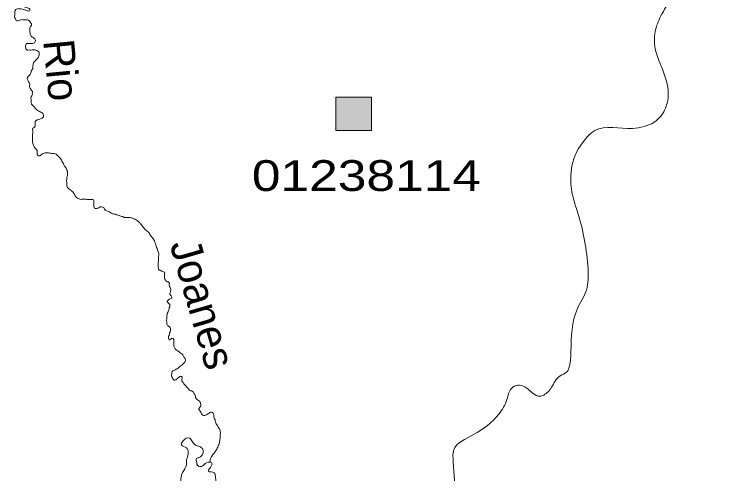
# Model space of a CAD drawing. Extents: x 854879 to 917879, y 8541948 to 8631048.
# Drawn here: x 893942 to 903256, y 8588549 to 8594513 of the extents above; entities that cross this region are included whole.
import ezdxf
from ezdxf.enums import TextEntityAlignment as Align

# ---------------------------------------------------------------- set-up
doc = ezdxf.new("R2010")
doc.units = 0
doc.header["$LTSCALE"] = 160
for name, color, linetype, lineweight in [('1', 7, 'Continuous', 13), ('12', 7, 'Continuous', 13), ('3', 7, 'Continuous', 13), ('63', 7, 'Continuous', 13)]:
    doc.layers.add(name, color=color, linetype=linetype, lineweight=lineweight)

msp = doc.modelspace()

# ---------------------------------------------------------------- hatches: boundary and pattern name
at = {"layer": '1'}
msp.add_hatch(color=256, dxfattribs=at).paths.add_polyline_path([(898118.1, 8593436.5), (898581.9, 8593436.5), (898581.9, 8593005.6), (898118.1, 8593005.6)])

# ---------------------------------------------------------------- linework, layer by layer
msp.add_lwpolyline([(898118.1, 8593436.5), (898581.9, 8593436.5), (898581.9, 8593005.6), (898118.1, 8593005.6)], close=True, dxfattribs=at)
at = {"layer": '12'}
msp.add_spline([(900643.9, 8584741.1), (900619.9, 8584871.4), (900626.7, 8585014), (900634.4, 8585228), (900780.5, 8585509.1), (900951, 8585695.6), (901064.4, 8585806.4), (901276.2, 8586035.7), (901382.7, 8586205.2), (901351.9, 8586399.2), (901212.2, 8586439.1), (901055.9, 8586586.3), (901008.8, 8586698.9), (900724.5, 8587015.8), (900510.3, 8587232.4), (900407, 8587327.9), (900324, 8587423.2), (900225.9, 8587541.6), (900060.1, 8587742.3), (899971.3, 8587779.1), (899833.8, 8587793.5), (899760.2, 8587824.9), (899717.6, 8587884.1), (899690.3, 8587948.1), (899670.9, 8588027.3), (899663.3, 8588246.6), (899640.6, 8588700.4), (899650.2, 8588860.9), (899902.3, 8589056.6), (900231.8, 8589322.8), (900338.6, 8589512.6), (900396.4, 8589657.2), (900478.5, 8589699.5), (900658.4, 8589608.2), (900741.9, 8589556.2), (900816, 8589570.6), (900916.6, 8589671.3), (901028, 8589817.8), (901115.3, 8589870.3), (901149.3, 8589946.3), (901169.4, 8590137.2), (901252.5, 8590691.7), (901370.1, 8590932.4), (901391.2, 8591209.9), (901259.6, 8591930.1), (901186.1, 8592183.3), (901168.7, 8592433.2), (901196.2, 8592601.1), (901235.7, 8592710.2), (901308.5, 8592829.1), (901478.8, 8593002.9), (901968.6, 8593032.7), (902119.3, 8593056.4), (902298.9, 8593151), (902374, 8593247), (902432.5, 8593450.1), (902372.4, 8593761.8), (902263.9, 8594071.4), (902261.4, 8594285.5), (902337.8, 8594493.5), (902402.9, 8594607.4), (902540.5, 8594814.7), (902654.2, 8594951), (902770.5, 8595079.5), (902868.5, 8595175.2), (903038.4, 8595313.3), (903090.1, 8595376.4), (903147.2, 8595462.4), (903192.1, 8595591.8), (903230.5, 8595820.7), (903229.4, 8596368.6), (903203, 8596509.1), (903123.7, 8596701.1), (902923.2, 8596772.3), (902650.6, 8596788.3), (902490.4, 8596820.8), (902359, 8596924.3), (902270.8, 8597009.5), (901875.8, 8597452.5), (901622.2, 8597565.1), (901225, 8597605.6), (901008.7, 8597636.2), (900474, 8597688.4), (900290, 8597655), (899741.3, 8597600.4), (899444.8, 8597537.7), (899235.4, 8597501.9), (899100.1, 8597485.7), (898970.1, 8597487.3), (898858.4, 8597526.8), (898709.6, 8597663.7)], degree=3, dxfattribs=at)
msp.add_spline([(900643.9, 8584741.1), (900619.9, 8584871.4), (900626.7, 8585014), (900634.4, 8585228), (900780.5, 8585509.1), (900951, 8585695.6), (901064.4, 8585806.4), (901276.2, 8586035.7), (901382.7, 8586205.2), (901351.9, 8586399.2), (901212.2, 8586439.1), (901055.9, 8586586.3), (901008.8, 8586698.9), (900724.5, 8587015.8), (900510.3, 8587232.4), (900407, 8587327.9), (900324, 8587423.2), (900225.9, 8587541.6), (900060.1, 8587742.3), (899971.3, 8587779.1), (899833.8, 8587793.5), (899760.2, 8587824.9), (899717.6, 8587884.1), (899690.3, 8587948.1), (899670.9, 8588027.3), (899663.3, 8588246.6), (899640.6, 8588700.4), (899650.2, 8588860.9), (899902.3, 8589056.6), (900231.8, 8589322.8), (900338.6, 8589512.6), (900396.4, 8589657.2), (900478.5, 8589699.5), (900658.4, 8589608.2), (900741.9, 8589556.2), (900816, 8589570.6), (900916.6, 8589671.3), (901028, 8589817.8), (901115.3, 8589870.3), (901149.3, 8589946.3), (901169.4, 8590137.2), (901252.5, 8590691.7), (901370.1, 8590932.4), (901391.2, 8591209.9), (901259.6, 8591930.1), (901186.1, 8592183.3), (901168.7, 8592433.2), (901196.2, 8592601.1), (901235.7, 8592710.2), (901308.5, 8592829.1), (901478.8, 8593002.9), (901968.6, 8593032.7), (902119.3, 8593056.4), (902298.9, 8593151), (902374, 8593247), (902432.5, 8593450.1), (902372.4, 8593761.8), (902263.9, 8594071.4), (902261.4, 8594285.5), (902337.8, 8594493.5), (902402.9, 8594607.4), (902540.5, 8594814.7), (902654.2, 8594951), (902770.5, 8595079.5), (902868.5, 8595175.2), (903038.4, 8595313.3), (903090.1, 8595376.4), (903147.2, 8595462.4), (903192.1, 8595591.8), (903230.5, 8595820.7), (903229.4, 8596368.6), (903203, 8596509.1), (903123.7, 8596701.1), (902923.2, 8596772.3), (902650.6, 8596788.3), (902490.4, 8596820.8), (902359, 8596924.3), (902270.8, 8597009.5), (901875.8, 8597452.5), (901622.2, 8597565.1), (901225, 8597605.6), (901008.7, 8597636.2), (900474, 8597688.4), (900290, 8597655), (899741.3, 8597600.4), (899444.8, 8597537.7), (899235.4, 8597501.9), (899100.1, 8597485.7), (898970.1, 8597487.3), (898858.4, 8597526.8), (898709.6, 8597663.7)], degree=3, dxfattribs=at)
at = {"layer": '3'}
for points in [[(894175.9, 8593485.7), (894176.9, 8593511.1), (894162.5, 8593532.1), (894148, 8593553.1), (894141.2, 8593573.8), (894142.1, 8593594.1), (894140.4, 8593617.1), (894126, 8593638.1), (894119.2, 8593658.8), (894109.8, 8593679.5), (894121.2, 8593707.1), (894139.6, 8593721.6), (894153.3, 8593744), (894159.3, 8593766.7), (894167.8, 8593786.7), (894181.4, 8593806.5), (894182.3, 8593829.4), (894186.1, 8593859.8), (894189.7, 8593885.2), (894210.9, 8593904.7), (894224.4, 8593921.9), (894243, 8593941.6), (894259.4, 8593968.9), (894265.7, 8593996.7), (894259.2, 8594025), (894234.5, 8594043.8), (894211.8, 8594052.4), (894186.4, 8594053.4), (894158.2, 8594049.5), (894137.8, 8594050.4), (894109.7, 8594049), (894092.6, 8594067.5), (894088.5, 8594093.2), (894089.4, 8594113.5), (894102.9, 8594133.3), (894128.5, 8594134.8), (894159.1, 8594133.6), (894179.5, 8594135.3), (894202.8, 8594141.9), (894213.8, 8594161.9), (894214.7, 8594184.8), (894200.1, 8594200.7), (894182.9, 8594216.7), (894160.5, 8594230.3), (894151, 8594248.6), (894146.9, 8594271.7), (894142.9, 8594299.8), (894144.1, 8594327.8), (894147.4, 8594348.1), (894166.5, 8594377.8), (894157.2, 8594398.6), (894142.7, 8594419.6), (894125.5, 8594435.6), (894092.6, 8594442.1), (894067.2, 8594443.1), (894041.7, 8594444.2), (894015.9, 8594437.6), (893987.5, 8594428.6), (893967.2, 8594432), (893958, 8594455.3), (893946, 8594473.6), (893947.2, 8594504.1), (893948.2, 8594529.6), (893949.2, 8594552.4), (893960.3, 8594574.9), (893981.2, 8594586.8), (894006.7, 8594585.8), (894032.1, 8594584.7), (894057.3, 8594576), (894090.1, 8594567), (894115.2, 8594558.3), (894138.2, 8594557.4), (894144.2, 8594580.1), (894124.3, 8594593.6), (894104.3, 8594602.1), (894081.6, 8594608.1), (894061.8, 8594624.2), (894042.1, 8594640.3), (894035.3, 8594661), (894043.7, 8594681), (894067.3, 8594695.3), (894075.8, 8594715.4), (894076.7, 8594738.3), (894095.6, 8594763), (894118.5, 8594762), (894146.6, 8594763.4), (894168.1, 8594790.6), (894161.3, 8594811.2), (894149.4, 8594832.1), (894135, 8594853.1), (894133.3, 8594873.5)], [(895017.7, 8591993.5), (894992.2, 8591992), (894977.5, 8592007.9), (894976.1, 8592036), (894974.6, 8592061.5), (894975.6, 8592084.4), (894968.8, 8592105.1), (894948.5, 8592108.5), (894928.1, 8592109.3), (894897.6, 8592110.6), (894874.6, 8592111.5), (894844.1, 8592112.8), (894813.4, 8592111.5), (894793, 8592112.3), (894773, 8592120.8), (894750.6, 8592134.5), (894733.6, 8592155.6), (894721.6, 8592173.9), (894709.8, 8592197.3), (894690.2, 8592218.5), (894668, 8592234.7), (894643.3, 8592256.1), (894626.2, 8592274.7), (894622, 8592295.2), (894622.9, 8592318.1), (894621.3, 8592341.1), (894622.3, 8592366.6), (894623.2, 8592386.9), (894629.2, 8592409.6), (894632.6, 8592429.8), (894633.5, 8592452.7), (894632, 8592478.3), (894617.8, 8592504.3), (894608.4, 8592525.1), (894593.9, 8592543.5), (894579.8, 8592574.7), (894567.8, 8592593), (894553.6, 8592619.1), (894536.8, 8592645.3), (894519.7, 8592663.8), (894502.5, 8592679.8), (894485.3, 8592695.8), (894460.2, 8592704.5), (894439.9, 8592707.9), (894417, 8592708.8), (894396.7, 8592712.2), (894371.2, 8592713.3), (894343.2, 8592714.4), (894320, 8592707.7), (894293.9, 8592693.5), (894275.3, 8592676.5), (894255, 8592677.3), (894240.4, 8592695.7), (894238.9, 8592721.3), (894239.9, 8592744.2), (894220.4, 8592767.9), (894201, 8592791.6), (894189, 8592810), (894182.4, 8592835.7), (894178.3, 8592861.4), (894179.3, 8592884.3), (894177.8, 8592909.8), (894178.8, 8592935.2), (894179.7, 8592955.6), (894180.7, 8592981), (894179.4, 8593011.7), (894182.9, 8593034.4), (894203.8, 8593046.3), (894212.7, 8593076.5), (894211.2, 8593102.1), (894214.5, 8593122.3), (894238.3, 8593141.7), (894261.5, 8593148.4), (894282.3, 8593157.7), (894305.6, 8593164.4), (894319.1, 8593184.2), (894320, 8593204.6), (894313.2, 8593225.2), (894290.8, 8593238.9), (894273.3, 8593249.8), (894248.5, 8593266.1), (894221.2, 8593285.1), (894199.4, 8593314), (894182.1, 8593327.5), (894165.1, 8593348.6), (894158.7, 8593376.9), (894159.5, 8593397.2), (894157.9, 8593420.2), (894161.4, 8593443), (894175, 8593465.4), (894175.9, 8593485.7)], [(895944.6, 8590334.7), (895955.7, 8590354.6), (895959.1, 8590377.4), (895967.9, 8590405.1), (895968.8, 8590425.4), (895967, 8590445.9), (895947.3, 8590462), (895923, 8590491), (895921.4, 8590514), (895919.7, 8590534.5), (895920.6, 8590557.4), (895921.4, 8590577.7), (895922.5, 8590603.2), (895928.6, 8590628.4), (895939.9, 8590655.9), (895948.4, 8590676), (895954.5, 8590701.2), (895963.4, 8590731.4), (895954.2, 8590754.7), (895934.4, 8590770.8), (895927.6, 8590791.5), (895943.5, 8590806.1), (895967.1, 8590820.4), (895987.9, 8590829.8), (895978.8, 8590858.2), (895961.8, 8590879.2), (895968.2, 8590909.6), (895974.2, 8590932.2), (895970.2, 8590957.9), (895958.3, 8590978.8), (895954.1, 8591001.9), (895955.1, 8591024.8), (895937.7, 8591038.2), (895917.7, 8591046.7), (895903, 8591062.6), (895891.4, 8591091.1), (895892.4, 8591114), (895893.4, 8591139.4), (895891.9, 8591164.9), (895864.2, 8591173.7), (895844.4, 8591187.3), (895824.2, 8591193.2), (895812.6, 8591221.7), (895808.6, 8591247.4), (895809.5, 8591270.3), (895810.6, 8591295.7), (895814.1, 8591321), (895815.2, 8591346.5), (895816.2, 8591371.9), (895817.2, 8591394.8), (895815.6, 8591417.8), (895806.4, 8591443.7), (895794.8, 8591472.2), (895785.7, 8591498), (895779, 8591521.2), (895769.6, 8591542), (895763.2, 8591572.8), (895743.9, 8591599.1), (895726.9, 8591620.2), (895705.2, 8591651.7), (895691, 8591677.8), (895668.9, 8591699), (895641.7, 8591720.6), (895622.1, 8591739.2), (895607.6, 8591757.6), (895593.1, 8591778.6), (895568.8, 8591807.7), (895546.7, 8591828.9), (895524.4, 8591845.2), (895499.3, 8591856.4), (895469.3, 8591870.4), (895444, 8591874), (895415.9, 8591875.1), (895395.6, 8591876), (895370.1, 8591877), (895347.6, 8591888.1), (895324.8, 8591891.6), (895302.2, 8591900.2), (895272, 8591911.6), (895244.3, 8591920.4), (895219, 8591924), (895198.9, 8591932.5), (895176.6, 8591948.7), (895154, 8591957.3), (895131.4, 8591965.9), (895114.2, 8591981.9), (895102.4, 8592005.3), (895079.8, 8592013.9), (895056.9, 8592014.8), (895038.5, 8592002.8), (895017.7, 8591993.5)], [(896484.1, 8588698.6), (896486.2, 8588735.2), (896500.1, 8588762.6), (896516.4, 8588787.4), (896527.3, 8588804.8), (896546.2, 8588829.5), (896562.5, 8588854.3), (896576.3, 8588879.2), (896590.3, 8588909.2), (896601.6, 8588936.8), (896607.6, 8588959.5), (896608.6, 8588982.3), (896614.6, 8589005), (896615.6, 8589030.5), (896616.8, 8589058.4), (896617.8, 8589083.9), (896613.8, 8589109.5), (896607, 8589130.2), (896590.1, 8589153.8), (896578.2, 8589174.7), (896563.7, 8589195.7), (896554.5, 8589219), (896548, 8589247.3), (896536.4, 8589275.8), (896532.2, 8589296.3), (896528.2, 8589324.5), (896516.3, 8589345.4), (896490.8, 8589346.5), (896469.9, 8589334.6), (896449, 8589320.2), (896425.5, 8589308.4), (896402.4, 8589304.3), (896379.9, 8589315.4), (896368.1, 8589338.8), (896356.2, 8589359.7), (896339.2, 8589380.8), (896345.2, 8589403.4), (896358.8, 8589423.3), (896362.3, 8589446.1), (896355.9, 8589476.9), (896333.9, 8589500.7), (896311.5, 8589514.4), (896294.6, 8589538), (896290.7, 8589566.2), (896278.8, 8589587.1), (896266.9, 8589608), (896244.6, 8589624.2), (896224.4, 8589630.1), (896204.8, 8589648.8), (896185.1, 8589667.4), (896168.1, 8589688.5), (896151, 8589707), (896126.9, 8589741.2), (896115.1, 8589764.6), (896121.1, 8589784.7), (896114.6, 8589813), (896089, 8589811.5), (896070.3, 8589791.9), (896049.2, 8589774.9), (896028.3, 8589763.1), (896008.3, 8589771.5), (895993.9, 8589795.1), (895984.6, 8589815.8), (895985.7, 8589843.8), (895989.2, 8589866.6), (896000.2, 8589886.5), (896023.5, 8589893.2), (896044.4, 8589905.1), (896067.9, 8589919.4), (896089.1, 8589938.9), (896115.4, 8589958.2), (896139.2, 8589977.6), (896155.3, 8589997.3), (896163.8, 8590017.3), (896159.6, 8590040.5), (896138, 8590074.5), (896118.8, 8590103.3), (896098.8, 8590114.3), (896081.7, 8590130.3), (896064.3, 8590143.8), (896032.2, 8590168), (896017.9, 8590194.1), (896011.2, 8590217.3), (896012.4, 8590245.3), (896013.3, 8590268.2), (896014.3, 8590291.1), (895994.5, 8590307.2), (895973.6, 8590295.3), (895952.9, 8590288.5), (895943.5, 8590306.7), (895944.6, 8590334.7)], [(898348.1, 8586162.4), (898285.4, 8586118.7), (898230.2, 8586074.7), (898183.5, 8585979.5), (898166.4, 8585929.1), (898147.1, 8585889), (897984.5, 8585690.8), (897930.9, 8585618.8), (897848.9, 8585535), (897788.6, 8585488.7), (897737.2, 8585477.8), (897626.6, 8585522.4), (897492.2, 8585613.8), (897472.8, 8585640), (897466.9, 8585688.6), (897498.5, 8585786.9), (897536.7, 8585859.5), (897628.2, 8585991.4), (897656.1, 8586059.2), (897668.9, 8586132.7), (897693.2, 8586241.4), (897706.2, 8586320), (897714, 8586393.6), (897723.4, 8586444.3), (897713.5, 8586523.7), (897689.1, 8586552.6), (897640.8, 8586556.8), (897530.8, 8586476.5), (897493, 8586488.1), (897464.3, 8586542.6), (897456.4, 8586606.6), (897428.3, 8586676.4), (897362.9, 8586699.1), (897295.8, 8586676), (897247.4, 8586677.7), (897228.1, 8586708.9), (897278.4, 8586832.1), (897300.5, 8586879.7), (897315.7, 8586948), (897264.9, 8587023.7), (897202.1, 8587048.8), (897137.2, 8587089.4), (897070.7, 8587152.9), (896968.8, 8587156.4), (896900.8, 8587107.8), (896880.2, 8587103.5), (896855.6, 8587127.3), (896855.6, 8587198.7), (896851.5, 8587298.2), (896889.2, 8587353), (896911.7, 8587410.8), (896919.9, 8587499.7), (896879.1, 8587712.7), (896836.2, 8587795.8), (896745.3, 8587890.7), (896698.1, 8587925.5), (896643, 8588024.3), (896620.7, 8588185.7), (896614.7, 8588231.8), (896622.7, 8588310.5), (896592, 8588380.4), (896563.8, 8588447.7), (896553.4, 8588511.8), (896537.3, 8588560.8), (896464.1, 8588581.2), (896508.7, 8588686.7), (896458.1, 8588698.7), (896387.6, 8588652.7), (896351.5, 8588641.2), (896321.5, 8588657.6), (896310.1, 8588693.7), (896309.3, 8588744.7), (896343.1, 8588761.3), (896374.4, 8588780.6), (896387.7, 8588866.8), (896360.7, 8588895.8), (896302.7, 8588915.7), (896253.5, 8588963.3), (896219.4, 8589010.3), (896128.9, 8588972.8), (896111.8, 8588922.4), (896176.7, 8588884.4), (896199.4, 8588807.1), (896178.6, 8588723.8), (896176.4, 8588662.7), (896127, 8588565), (896104.8, 8588443.4), (896144.2, 8588335), (896173.3, 8588293.2), (896261.8, 8588272.2), (896320.9, 8588214.1)]]:
    msp.add_spline(points, degree=3, dxfattribs=at)
at = {"layer": '63'}
msp.add_spline([(900643.9, 8584741.1), (900619.9, 8584871.4), (900626.7, 8585014), (900634.4, 8585228), (900780.5, 8585509.1), (900951, 8585695.6), (901064.4, 8585806.4), (901276.2, 8586035.7), (901382.7, 8586205.2), (901351.9, 8586399.2), (901212.2, 8586439.1), (901055.9, 8586586.3), (901008.8, 8586698.9), (900724.5, 8587015.8), (900510.3, 8587232.4), (900407, 8587327.9), (900324, 8587423.2), (900225.9, 8587541.6), (900060.1, 8587742.3), (899971.3, 8587779.1), (899833.8, 8587793.5), (899760.2, 8587824.9), (899717.6, 8587884.1), (899690.3, 8587948.1), (899670.9, 8588027.3), (899663.3, 8588246.6), (899640.6, 8588700.4), (899650.2, 8588860.9), (899902.3, 8589056.6), (900231.8, 8589322.8), (900338.6, 8589512.6), (900396.4, 8589657.2), (900478.5, 8589699.5), (900658.4, 8589608.2), (900741.9, 8589556.2), (900816, 8589570.6), (900916.6, 8589671.3), (901028, 8589817.8), (901115.3, 8589870.3), (901149.3, 8589946.3), (901169.4, 8590137.2), (901252.5, 8590691.7), (901370.1, 8590932.4), (901391.2, 8591209.9), (901259.6, 8591930.1), (901186.1, 8592183.3), (901168.7, 8592433.2), (901196.2, 8592601.1), (901235.7, 8592710.2), (901308.5, 8592829.1), (901478.8, 8593002.9), (901968.6, 8593032.7), (902119.3, 8593056.4), (902298.9, 8593151), (902374, 8593247), (902432.5, 8593450.1), (902372.4, 8593761.8), (902263.9, 8594071.4), (902261.4, 8594285.5), (902337.8, 8594493.5), (902402.9, 8594607.4), (902540.5, 8594814.7), (902654.2, 8594951), (902770.5, 8595079.5), (902868.5, 8595175.2), (903038.4, 8595313.3), (903090.1, 8595376.4), (903147.2, 8595462.4), (903192.1, 8595591.8), (903230.5, 8595820.7), (903229.4, 8596368.6), (903203, 8596509.1), (903123.7, 8596701.1), (902923.2, 8596772.3), (902650.6, 8596788.3), (902490.4, 8596820.8), (902359, 8596924.3), (902270.8, 8597009.5), (901875.8, 8597452.5), (901622.2, 8597565.1), (901225, 8597605.6), (901008.7, 8597636.2), (900474, 8597688.4), (900290, 8597655), (899741.3, 8597600.4), (899444.8, 8597537.7), (899235.4, 8597501.9), (899100.1, 8597485.7), (898970.1, 8597487.3), (898858.4, 8597526.8), (898709.6, 8597663.7)], degree=3, dxfattribs=at)

# ---------------------------------------------------------------- texts
at = {"layer": '1'}
for s, rotation, p in [('Rio', 275.5, (894316.4, 8594170.7)), ('Joanes', 286.228, (895956.8, 8591527.3))]:
    msp.add_text(s, height=400, rotation=rotation, dxfattribs=at).set_placement(p)
at = {"layer": '1', "width": 1.25}
msp.add_text('01238114', height=400, dxfattribs=at).set_placement((898513.9, 8592219.8), align=Align.CENTER)

doc.saveas('drawing.dxf')
